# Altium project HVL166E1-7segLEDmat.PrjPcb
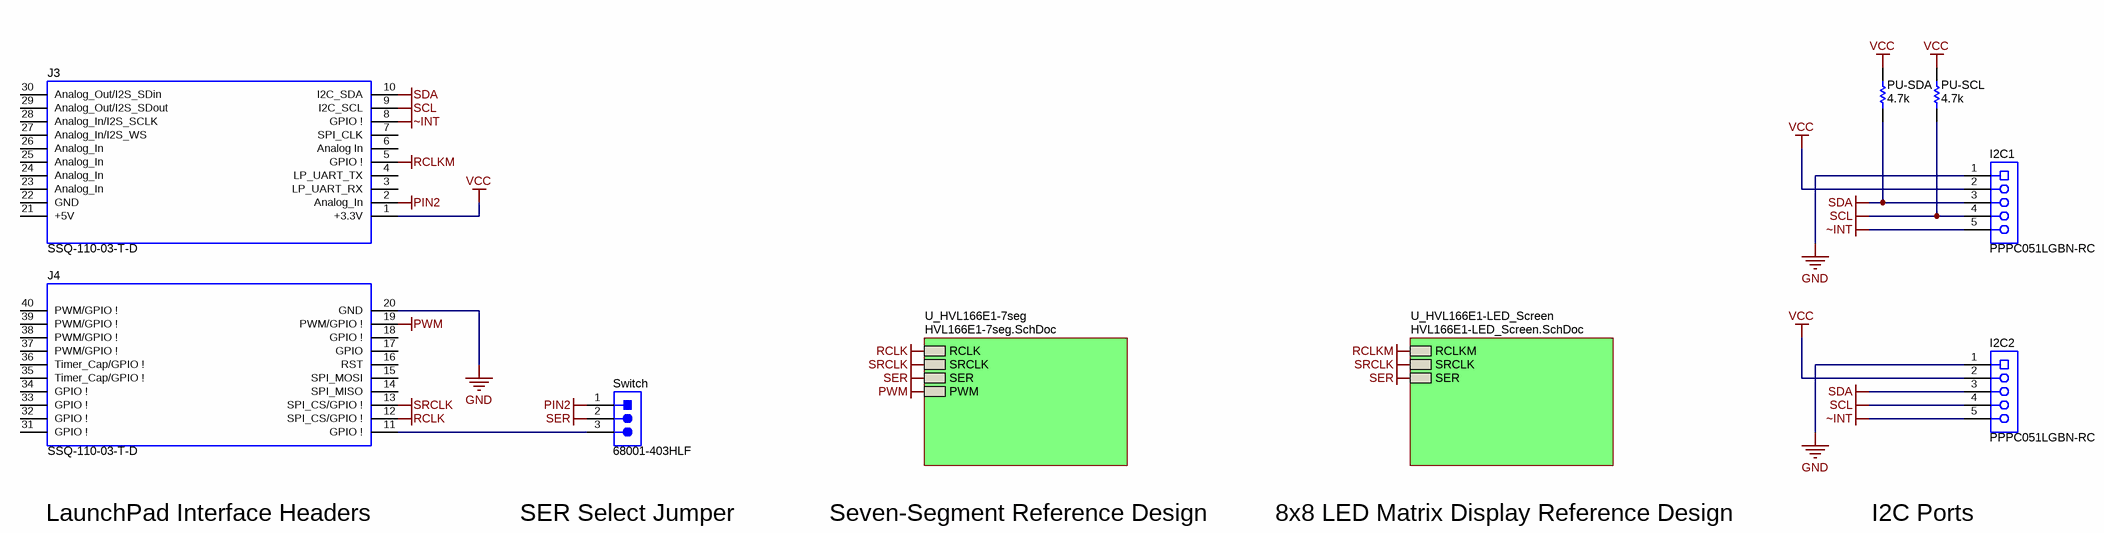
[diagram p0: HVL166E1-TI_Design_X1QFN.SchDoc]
CopyrightYear: 2016; PCB_Layout: Daniel Hartung; PCB_Rev: E1; PRJ_Customer: Public Release; PRJ_Engineer: Daniel Hartung; PRJ_Number: HVL166; PRJ_Title: BOOSTXL-SHIFTLED; SCH_Rev: E1; TechSupport: http://www.ti.com/support; TID: TIDA-1233
3 sheets, 193 parts. Net scope: hierarchical (ports join the sheet entries above them; power ports are global).
Board file: HVL166E1-7SegPCB.PcbDoc
Sheets:
  HVL166E1-TI_Design_X1QFN.SchDoc
    U_HVL166E1-7seg = HVL166E1-7seg.SchDoc
    U_HVL166E1-LED_Screen = HVL166E1-LED_Screen.SchDoc

## Sheet HVL166E1-TI_Design_X1QFN.SchDoc
size 431 x 279 mm; Date: Not shown in title block; ApprovedBy: Not shown in title block; CheckedBy: Not shown in title block; Author: Not shown in title block; CompanyName: Not shown in title block; Engineer: Not shown in title block; Organization: Not shown in title block; Address1: Not shown in title block; Address2: Not shown in title block; Address3: Not shown in title block; Address4: Not shown in title block; DocumentNumber: 1; Revision: Use project parameter SCH_Rev; SheetNumber: 1; SheetTotal: 3; PageSetup: Record=PageOptions¦CenterHorizontal=True¦CenterVertical=True¦PrintScale=1.00¦XCorrection=1.00¦YCorrection=1.00¦PrintKind=0¦BorderSize=5000000¦LeftOffset=0¦BottomOffset=0¦Orientation=2¦PaperLength=1000¦PaperWidth=1000¦Scale=100¦PaperSource=15¦PrintQuality=600¦MediaType=1¦DitherType=10¦PaperKind=Letter¦PrintScaleMode=1

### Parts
I2C1  PPPC051LGBN-RC  [CONN_PPPC051LGBN]
I2C2  PPPC051LGBN-RC  [CONN_PPPC051LGBN]
J3  SSQ-110-03-T-D  [BoosterPack_40pin_J1J3]
J4  SSQ-110-03-T-D  [BoosterPack_40pin_J2J4]
PU-SCL  ValueDisplayed: 4.7k  [0603]  (hidden comment: CRCW06034K70JNEA)
PU-SDA  ValueDisplayed: 4.7k  [0603]  (hidden comment: CRCW06034K70JNEA)
Switch  68001-403HLF  [FCI_68001-403HLF]

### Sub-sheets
U_HVL166E1-7seg = HVL166E1-7seg.SchDoc: RCLK, SRCLK, SER, PWM
U_HVL166E1-LED_Screen = HVL166E1-LED_Screen.SchDoc: RCLKM, SRCLK, SER

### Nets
GND: I2C1.1 I2C2.1 J4.20(GND)
PIN2: J3.2(Analog_In) Switch.1
PWM: J4.19(PWM/GPIO_!) ; sheet U_HVL166E1-7seg/PWM
RCLK: J4.12(SPI_CS/GPIO_!) ; sheet U_HVL166E1-7seg/RCLK
RCLKM: J3.5(GPIO_!) ; sheet U_HVL166E1-LED_Screen/RCLKM
SCL: I2C1.4 I2C2.4 J3.9(I2C_SCL) PU-SCL.1
SDA: I2C1.3 I2C2.3 J3.10(I2C_SDA) PU-SDA.1
SER: Switch.2 ; sheet U_HVL166E1-7seg/SER, sheet U_HVL166E1-LED_Screen/SER
SRCLK: J4.13(SPI_CS/GPIO_!) ; sheet U_HVL166E1-7seg/SRCLK, sheet U_HVL166E1-LED_Screen/SRCLK
VCC: I2C1.2 I2C2.2 J3.1(+3.3V) PU-SCL.2 PU-SDA.2
~INT: I2C1.5 I2C2.5 J3.8(GPIO_!)
NetJ4_11: J4.11(GPIO_!) Switch.3

Not connected (* = marked no-connect by the designer): J3 3(LP_UART_RX) 4(LP_UART_TX) 6(Analog_In) 7(SPI_CLK) 21(+5V) 22(GND) 23(Analog_In) 24(Analog_In) 25(Analog_In) 26(Analog_In) 27(Analog_In/I2S_WS) 28(Analog_In/I2S_SCLK) 29(Analog_Out/I2S_SDout) 30(Analog_Out/I2S_SDin); J4 14(SPI_MISO) 15(SPI_MOSI) 16(RST) 17(GPIO) 18(GPIO_!) 31(GPIO_!) 32(GPIO_!) 33(GPIO_!) 34(GPIO_!) 35(Timer_Cap/GPIO_!) 36(Timer_Cap/GPIO_!) 37(PWM/GPIO_!) 38(PWM/GPIO_!) 39(PWM/GPIO_!) 40(PWM/GPIO_!)

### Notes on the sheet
- LaunchPad Interface Headers
- SER Select Jumper
- Seven-Segment Reference Design
- 8x8 LED Matrix Display Reference Design
- I2C Ports

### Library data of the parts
I2C1 I2C2 = PPPC051LGBN-RC: Receptacle, 100mil, 5x1, Gold, R/A, TH; Manufacturer: Sullins Connector Solutions; SymbolCreator: a0412235
J3 = BoosterPack_40pin_J1J3: Receptacle, 2.54mm, 10x2, Tin, TH; Manufacturer: Samtec; Alternate Manufacturer: Major League Electronics; Alternate PartNumber: CRD-081413-A-G; SymbolCreator: a0412235; Note: Booster Pack 40 pin J1 and J3
J4 = BoosterPack_40pin_J2J4: Receptacle, 2.54mm, 10x2, Tin, TH; Manufacturer: Samtec; Alternate Manufacturer: Major League Electronics; Alternate PartNumber: CRD-081413-A-G; SymbolCreator: a0412235; Note: Booster Pack 40 pin J2 and J4
PU-SCL PU-SDA = CRCW06034K70JNEA: RES, 4.7 k, 5%, 0.1 W, 0603; Manufacturer: Vishay-Dale; CompType: Resistor; Value: 4.7k; Res_ohm: 4700; Value_Code: 4k70; Tolerance_%: 5; Power_W: 0.1; Value2: 0.1W; VDC_V: 75; TempCo: 200 ppm/C; SizeArea_mm2: 1.28; SizeX_mm: 1.6; SizeY_mm: 0.8; SizeZ_mm: 1; EIA_Code: E24; U/M: EA; AEC Category: Q200
Switch = 68001-403HLF: Header, 2.54mm, 3x1, Tin, TH; Manufacturer: FCI; SymbolCreator: a0799628; Pitch_mm: 2.54; Gender: Male; Shrouded: N; Row_Count: 1; Current_A: 3; Voltage_V: 1500; Cert_CSA: Y

## Sheet HVL166E1-7seg.SchDoc
size 431 x 279 mm; Date: Not shown in title block; ApprovedBy: Not shown in title block; CheckedBy: Not shown in title block; Author: Not shown in title block; CompanyName: Not shown in title block; Engineer: Not shown in title block; Organization: Not shown in title block; Address1: Not shown in title block; Address2: Not shown in title block; Address3: Not shown in title block; Address4: Not shown in title block; DocumentNumber: 1; Revision: Use project parameter SCH_Rev; SheetNumber: 2; SheetTotal: 3; PageSetup: Record=PageOptions¦CenterHorizontal=True¦CenterVertical=True¦PrintScale=1.00¦XCorrection=1.00¦YCorrection=1.00¦PrintKind=0¦BorderSize=5000000¦LeftOffset=0¦BottomOffset=0¦Orientation=2¦PaperLength=1000¦PaperWidth=1000¦Scale=100¦PaperSource=15¦PrintQuality=600¦MediaType=1¦DitherType=10¦PaperKind=Letter¦PrintScaleMode=1
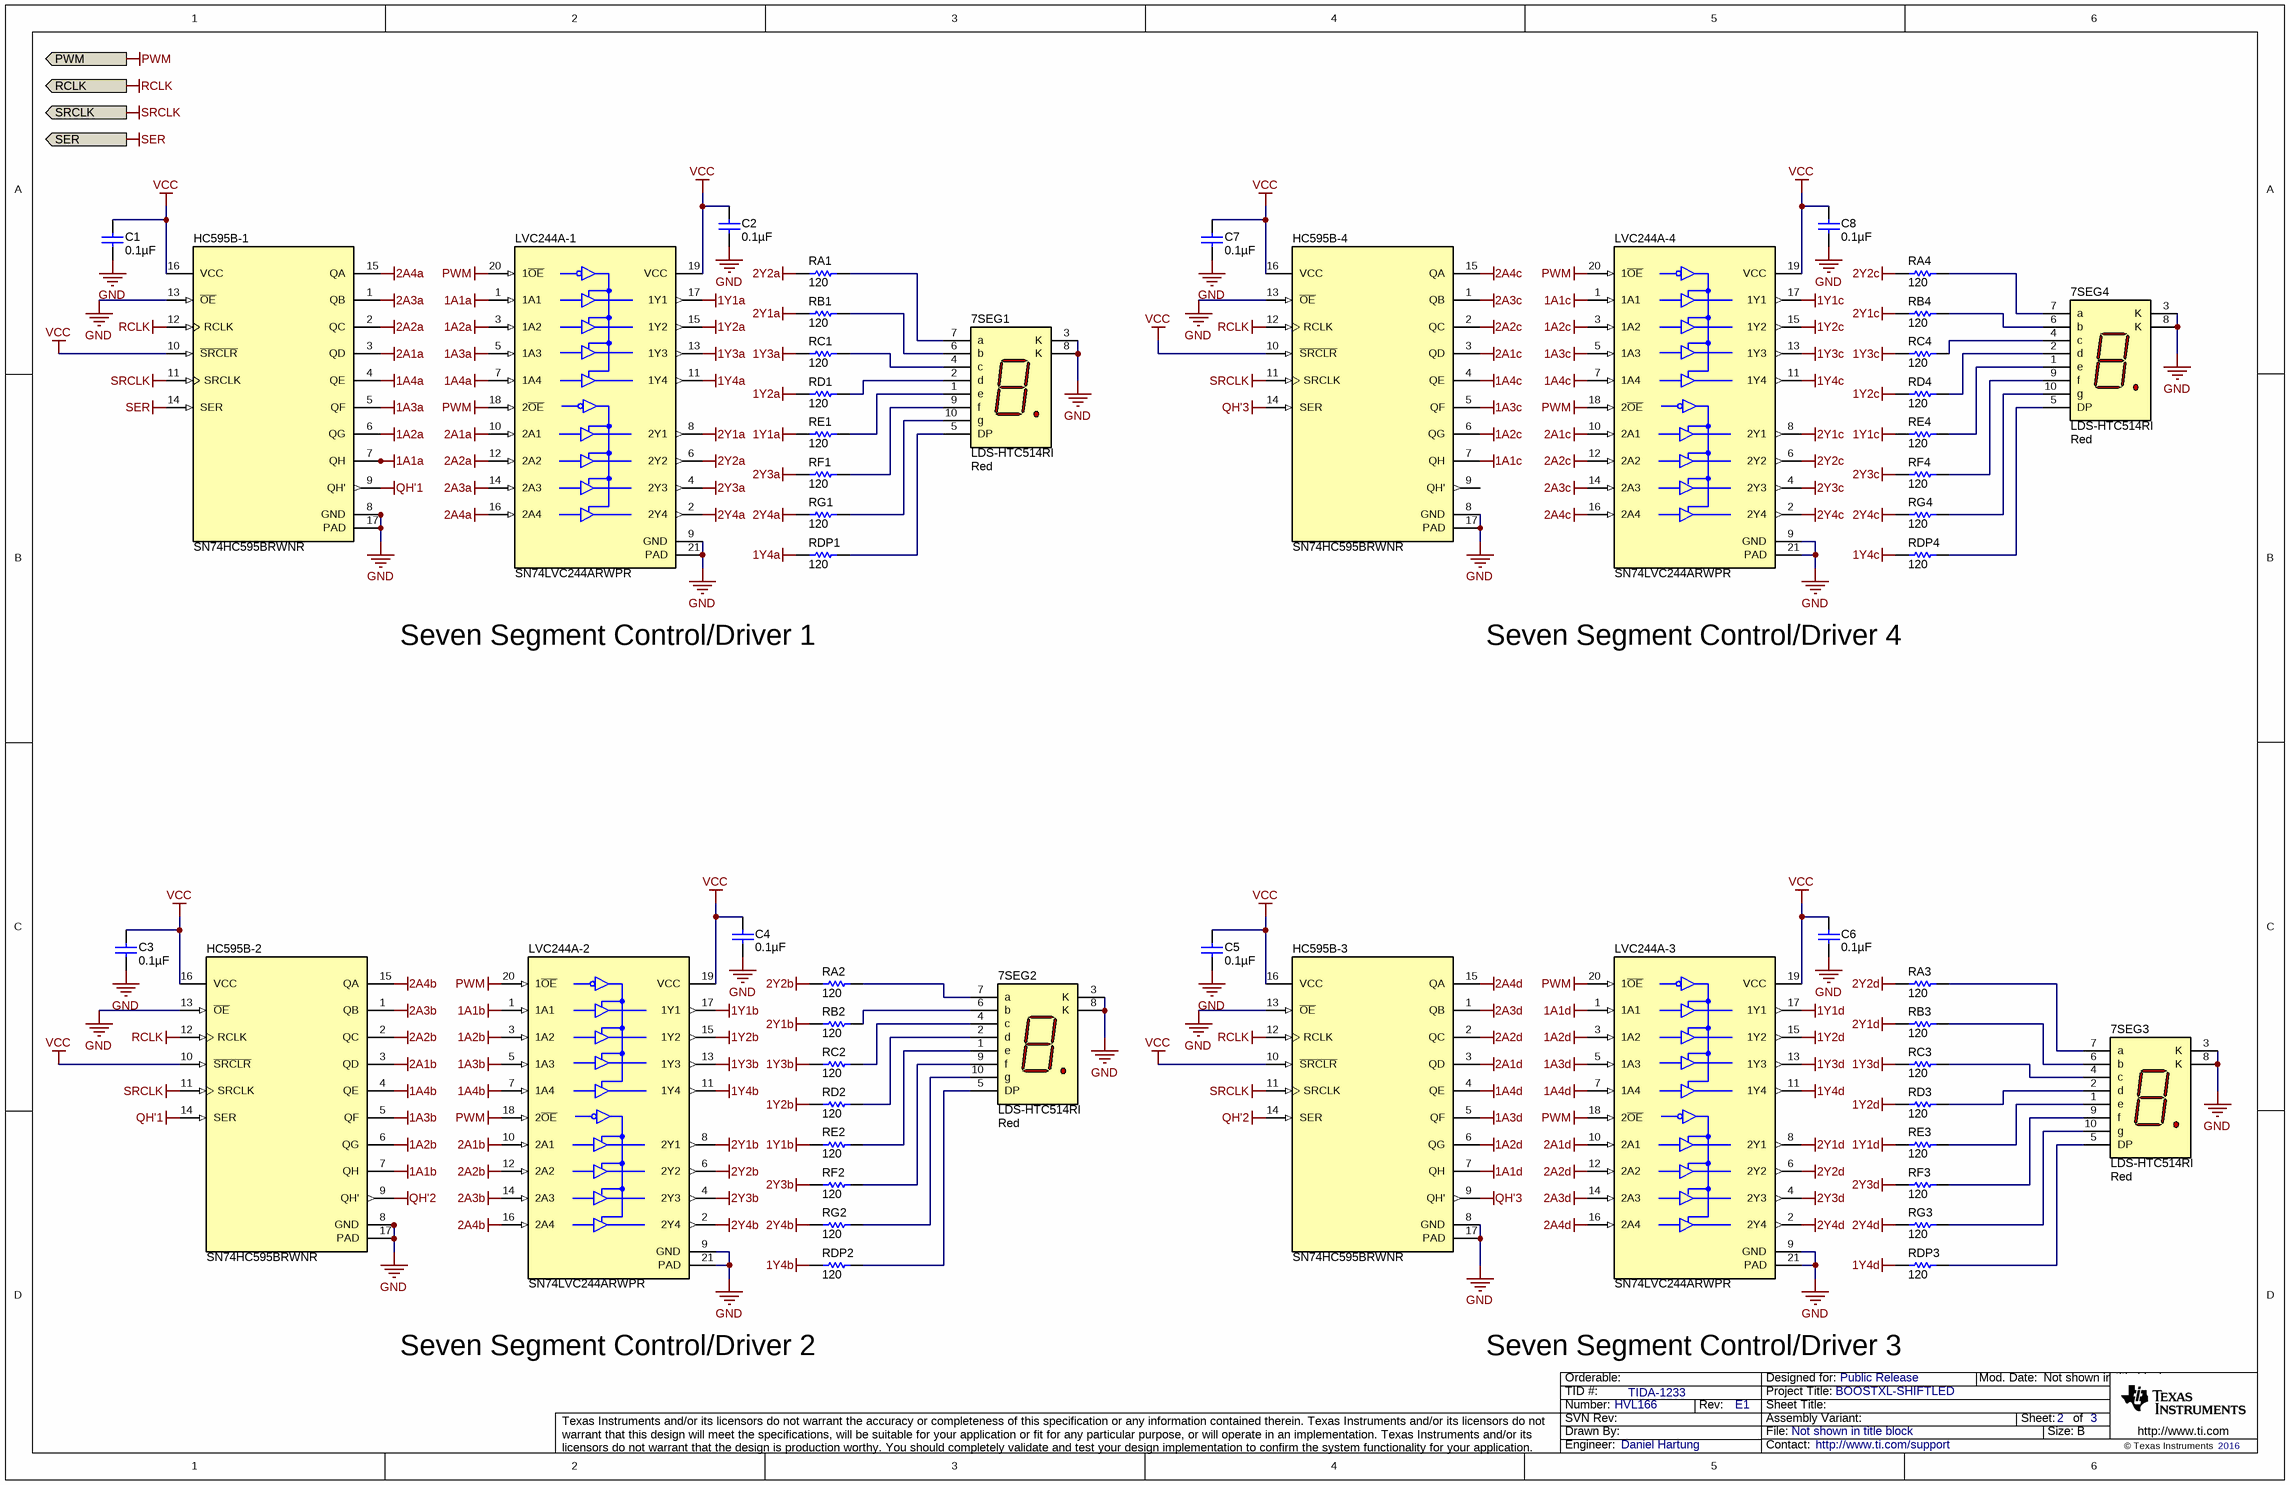
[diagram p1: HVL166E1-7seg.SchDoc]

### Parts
(Parts that share a designator on the sheet are numbered #1, #2 ... from top to bottom, then left to right.)
7SEG1  LDS-HTC514RI  value Red  [LDS-A514RI_Red]
7SEG2  LDS-HTC514RI  value Red  [LDS-A514RI_Red]
7SEG3  LDS-HTC514RI  value Red  [LDS-A514RI_Red]
7SEG4  LDS-HTC514RI  value Red  [LDS-A514RI_Red]
C1  ValueDisplayed: 0.1µF  [0402_065]  (hidden comment: 160R07X104KV4T)
C2  ValueDisplayed: 0.1µF  [0402_065]  (hidden comment: 160R07X104KV4T)
C3  ValueDisplayed: 0.1µF  [0402_065]  (hidden comment: 160R07X104KV4T)
C4  ValueDisplayed: 0.1µF  [0402_065]  (hidden comment: 160R07X104KV4T)
C5  ValueDisplayed: 0.1µF  [0402_065]  (hidden comment: 160R07X104KV4T)
C6  ValueDisplayed: 0.1µF  [0402_065]  (hidden comment: 160R07X104KV4T)
C7  ValueDisplayed: 0.1µF  [0402_065]  (hidden comment: 160R07X104KV4T)
C8  ValueDisplayed: 0.1µF  [0402_065]  (hidden comment: 160R07X104KV4T)
HC595B-1  SN74HC595BRWNR  [RWN0016A]
HC595B-2  SN74HC595BRWNR  [RWN0016A]
HC595B-3  SN74HC595BRWNR  [RWN0016A]
HC595B-4  SN74HC595BRWNR  [RWN0016A]
LVC244A-1  SN74LVC244ARWPR  [RWP0020A]
LVC244A-2  SN74LVC244ARWPR  [RWP0020A]
LVC244A-3  SN74LVC244ARWPR  [RWP0020A]
LVC244A-4  SN74LVC244ARWPR  [RWP0020A]
RA1#1  ValueDisplayed: 120  [0402]  (hidden comment: CRCW0402120RJNED)
RA2#1  ValueDisplayed: 120  [0402]  (hidden comment: CRCW0402120RJNED)
RA3#1  ValueDisplayed: 120  [0402]  (hidden comment: CRCW0402120RJNED)
RA4#1  ValueDisplayed: 120  [0402]  (hidden comment: CRCW0402120RJNED)
RB1#1  ValueDisplayed: 120  [0402]  (hidden comment: CRCW0402120RJNED)
RB2#1  ValueDisplayed: 120  [0402]  (hidden comment: CRCW0402120RJNED)
RB3#1  ValueDisplayed: 120  [0402]  (hidden comment: CRCW0402120RJNED)
RB4#1  ValueDisplayed: 120  [0402]  (hidden comment: CRCW0402120RJNED)
RC1#1  ValueDisplayed: 120  [0402]  (hidden comment: CRCW0402120RJNED)
RC2#1  ValueDisplayed: 120  [0402]  (hidden comment: CRCW0402120RJNED)
RC3#1  ValueDisplayed: 120  [0402]  (hidden comment: CRCW0402120RJNED)
RC4#1  ValueDisplayed: 120  [0402]  (hidden comment: CRCW0402120RJNED)
RD1#1  ValueDisplayed: 120  [0402]  (hidden comment: CRCW0402120RJNED)
RD2#1  ValueDisplayed: 120  [0402]  (hidden comment: CRCW0402120RJNED)
RD3#1  ValueDisplayed: 120  [0402]  (hidden comment: CRCW0402120RJNED)
RD4#1  ValueDisplayed: 120  [0402]  (hidden comment: CRCW0402120RJNED)
RDP1  ValueDisplayed: 120  [0402]  (hidden comment: CRCW0402120RJNED)
RDP2  ValueDisplayed: 120  [0402]  (hidden comment: CRCW0402120RJNED)
RDP3  ValueDisplayed: 120  [0402]  (hidden comment: CRCW0402120RJNED)
RDP4  ValueDisplayed: 120  [0402]  (hidden comment: CRCW0402120RJNED)
RE1#1  ValueDisplayed: 120  [0402]  (hidden comment: CRCW0402120RJNED)
RE2#1  ValueDisplayed: 120  [0402]  (hidden comment: CRCW0402120RJNED)
RE3#1  ValueDisplayed: 120  [0402]  (hidden comment: CRCW0402120RJNED)
RE4#1  ValueDisplayed: 120  [0402]  (hidden comment: CRCW0402120RJNED)
RF1#1  ValueDisplayed: 120  [0402]  (hidden comment: CRCW0402120RJNED)
RF2#1  ValueDisplayed: 120  [0402]  (hidden comment: CRCW0402120RJNED)
RF3#1  ValueDisplayed: 120  [0402]  (hidden comment: CRCW0402120RJNED)
RF4#1  ValueDisplayed: 120  [0402]  (hidden comment: CRCW0402120RJNED)
RG1#1  ValueDisplayed: 120  [0402]  (hidden comment: CRCW0402120RJNED)
RG2#1  ValueDisplayed: 120  [0402]  (hidden comment: CRCW0402120RJNED)
RG3#1  ValueDisplayed: 120  [0402]  (hidden comment: CRCW0402120RJNED)
RG4#1  ValueDisplayed: 120  [0402]  (hidden comment: CRCW0402120RJNED)

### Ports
PWM, RCLK, SER, SRCLK

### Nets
1A1a: HC595B-1.7(QH) LVC244A-1.1(1A1)
1A1b: HC595B-2.7(QH) LVC244A-2.1(1A1)
1A1c: HC595B-4.7(QH) LVC244A-4.1(1A1)
1A1d: HC595B-3.7(QH) LVC244A-3.1(1A1)
1A2a: HC595B-1.6(QG) LVC244A-1.3(1A2)
1A2b: HC595B-2.6(QG) LVC244A-2.3(1A2)
1A2c: HC595B-4.6(QG) LVC244A-4.3(1A2)
1A2d: HC595B-3.6(QG) LVC244A-3.3(1A2)
1A3a: HC595B-1.5(QF) LVC244A-1.5(1A3)
1A3b: HC595B-2.5(QF) LVC244A-2.5(1A3)
1A3c: HC595B-4.5(QF) LVC244A-4.5(1A3)
1A3d: HC595B-3.5(QF) LVC244A-3.5(1A3)
1A4a: HC595B-1.4(QE) LVC244A-1.7(1A4)
1A4b: HC595B-2.4(QE) LVC244A-2.7(1A4)
1A4c: HC595B-4.4(QE) LVC244A-4.7(1A4)
1A4d: HC595B-3.4(QE) LVC244A-3.7(1A4)
1Y1a: LVC244A-1.17(1Y1) RE1#1.1
1Y1b: LVC244A-2.17(1Y1) RE2#1.1
1Y1c: LVC244A-4.17(1Y1) RE4#1.1
1Y1d: LVC244A-3.17(1Y1) RE3#1.1
1Y2a: LVC244A-1.15(1Y2) RD1#1.1
1Y2b: LVC244A-2.15(1Y2) RD2#1.1
1Y2c: LVC244A-4.15(1Y2) RD4#1.1
1Y2d: LVC244A-3.15(1Y2) RD3#1.1
1Y3a: LVC244A-1.13(1Y3) RC1#1.1
1Y3b: LVC244A-2.13(1Y3) RC2#1.1
1Y3c: LVC244A-4.13(1Y3) RC4#1.1
1Y3d: LVC244A-3.13(1Y3) RC3#1.1
1Y4a: LVC244A-1.11(1Y4) RDP1.1
1Y4b: LVC244A-2.11(1Y4) RDP2.1
1Y4c: LVC244A-4.11(1Y4) RDP4.1
1Y4d: LVC244A-3.11(1Y4) RDP3.1
2A1a: HC595B-1.3(QD) LVC244A-1.10(2A1)
2A1b: HC595B-2.3(QD) LVC244A-2.10(2A1)
2A1c: HC595B-4.3(QD) LVC244A-4.10(2A1)
2A1d: HC595B-3.3(QD) LVC244A-3.10(2A1)
2A2a: HC595B-1.2(QC) LVC244A-1.12(2A2)
2A2b: HC595B-2.2(QC) LVC244A-2.12(2A2)
2A2c: HC595B-4.2(QC) LVC244A-4.12(2A2)
2A2d: HC595B-3.2(QC) LVC244A-3.12(2A2)
2A3a: HC595B-1.1(QB) LVC244A-1.14(2A3)
2A3b: HC595B-2.1(QB) LVC244A-2.14(2A3)
2A3c: HC595B-4.1(QB) LVC244A-4.14(2A3)
2A3d: HC595B-3.1(QB) LVC244A-3.14(2A3)
2A4a: HC595B-1.15(QA) LVC244A-1.16(2A4)
2A4b: HC595B-2.15(QA) LVC244A-2.16(2A4)
2A4c: HC595B-4.15(QA) LVC244A-4.16(2A4)
2A4d: HC595B-3.15(QA) LVC244A-3.16(2A4)
2Y1a: LVC244A-1.8(2Y1) RB1#1.1
2Y1b: LVC244A-2.8(2Y1) RB2#1.1
2Y1c: LVC244A-4.8(2Y1) RB4#1.1
2Y1d: LVC244A-3.8(2Y1) RB3#1.1
2Y2a: LVC244A-1.6(2Y2) RA1#1.1
2Y2b: LVC244A-2.6(2Y2) RA2#1.1
2Y2c: LVC244A-4.6(2Y2) RA4#1.1
2Y2d: LVC244A-3.6(2Y2) RA3#1.1
2Y3a: LVC244A-1.4(2Y3) RF1#1.1
2Y3b: LVC244A-2.4(2Y3) RF2#1.1
2Y3c: LVC244A-4.4(2Y3) RF4#1.1
2Y3d: LVC244A-3.4(2Y3) RF3#1.1
2Y4a: LVC244A-1.2(2Y4) RG1#1.1
2Y4b: LVC244A-2.2(2Y4) RG2#1.1
2Y4c: LVC244A-4.2(2Y4) RG4#1.1
2Y4d: LVC244A-3.2(2Y4) RG3#1.1
GND: 7SEG1.3(K) 7SEG1.8(K) 7SEG2.3(K) 7SEG2.8(K) 7SEG3.3(K) 7SEG3.8(K) 7SEG4.3(K) 7SEG4.8(K) C1.2 C2.2 C3.2 C4.2 C5.2 C6.2 C7.2 C8.2 HC595B-1.8(GND) HC595B-1.13(~{OE}) HC595B-1.17(PAD) HC595B-2.8(GND) HC595B-2.13(~{OE}) HC595B-2.17(PAD) HC595B-3.8(GND) HC595B-3.13(~{OE}) HC595B-3.17(PAD) HC595B-4.8(GND) HC595B-4.13(~{OE}) HC595B-4.17(PAD) LVC244A-1.9(GND) LVC244A-1.21(PAD) LVC244A-2.9(GND) LVC244A-2.21(PAD) LVC244A-3.9(GND) LVC244A-3.21(PAD) LVC244A-4.9(GND) LVC244A-4.21(PAD)
PWM: LVC244A-1.18(2~{OE}) LVC244A-1.20(1~{OE}) LVC244A-2.18(2~{OE}) LVC244A-2.20(1~{OE}) LVC244A-3.18(2~{OE}) LVC244A-3.20(1~{OE}) LVC244A-4.18(2~{OE}) LVC244A-4.20(1~{OE}) ; port PWM
QH'1: HC595B-1.9(QH') HC595B-2.14(SER)
QH'2: HC595B-2.9(QH') HC595B-3.14(SER)
QH'3: HC595B-3.9(QH') HC595B-4.14(SER)
RCLK: HC595B-1.12(RCLK) HC595B-2.12(RCLK) HC595B-3.12(RCLK) HC595B-4.12(RCLK) ; port RCLK
SER: HC595B-1.14(SER) ; port SER
SRCLK: HC595B-1.11(SRCLK) HC595B-2.11(SRCLK) HC595B-3.11(SRCLK) HC595B-4.11(SRCLK) ; port SRCLK
VCC: C1.1 C2.1 C3.1 C4.1 C5.1 C6.1 C7.1 C8.1 HC595B-1.10(~{SRCLR}) HC595B-1.16(VCC) HC595B-2.10(~{SRCLR}) HC595B-2.16(VCC) HC595B-3.10(~{SRCLR}) HC595B-3.16(VCC) HC595B-4.10(~{SRCLR}) HC595B-4.16(VCC) LVC244A-1.19(VCC) LVC244A-2.19(VCC) LVC244A-3.19(VCC) LVC244A-4.19(VCC)
Net7SEG1_1: 7SEG1.1(e) RE1#1.2
Net7SEG1_2: 7SEG1.2(d) RD1#1.2
Net7SEG1_4: 7SEG1.4(c) RC1#1.2
Net7SEG1_5: 7SEG1.5(DP) RDP1.2
Net7SEG1_6: 7SEG1.6(b) RB1#1.2
Net7SEG1_7: 7SEG1.7(a) RA1#1.2
Net7SEG1_9: 7SEG1.9(f) RF1#1.2
Net7SEG1_10: 7SEG1.10(g) RG1#1.2
Net7SEG2_1: 7SEG2.1(e) RE2#1.2
Net7SEG2_2: 7SEG2.2(d) RD2#1.2
Net7SEG2_4: 7SEG2.4(c) RC2#1.2
Net7SEG2_5: 7SEG2.5(DP) RDP2.2
Net7SEG2_6: 7SEG2.6(b) RB2#1.2
Net7SEG2_7: 7SEG2.7(a) RA2#1.2
Net7SEG2_9: 7SEG2.9(f) RF2#1.2
Net7SEG2_10: 7SEG2.10(g) RG2#1.2
Net7SEG3_1: 7SEG3.1(e) RE3#1.2
Net7SEG3_2: 7SEG3.2(d) RD3#1.2
Net7SEG3_4: 7SEG3.4(c) RC3#1.2
Net7SEG3_5: 7SEG3.5(DP) RDP3.2
Net7SEG3_6: 7SEG3.6(b) RB3#1.2
Net7SEG3_7: 7SEG3.7(a) RA3#1.2
Net7SEG3_9: 7SEG3.9(f) RF3#1.2
Net7SEG3_10: 7SEG3.10(g) RG3#1.2
Net7SEG4_1: 7SEG4.1(e) RE4#1.2
Net7SEG4_2: 7SEG4.2(d) RD4#1.2
Net7SEG4_4: 7SEG4.4(c) RC4#1.2
Net7SEG4_5: 7SEG4.5(DP) RDP4.2
Net7SEG4_6: 7SEG4.6(b) RB4#1.2
Net7SEG4_7: 7SEG4.7(a) RA4#1.2
Net7SEG4_9: 7SEG4.9(f) RF4#1.2
Net7SEG4_10: 7SEG4.10(g) RG4#1.2

Not connected (* = marked no-connect by the designer): HC595B-4 9(QH')

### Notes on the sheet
- Seven Segment Control/Driver 1
- Seven Segment Control/Driver 4
- Seven Segment Control/Driver 2
- Seven Segment Control/Driver 3

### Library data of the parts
7SEG1-7SEG4 = LDS-HTC514RI: LED, Red, TH; Manufacturer: Lumex; SymbolCreator: Altium; Vf_V: 2.1; Value2: 2.1V; Io_A: 0.01; Vr_V: 5; Ir_A: 0.0001; Tjmax_C: 105; Power_TotalModule: 0.105; Value1: 0.105W; SizeAreaWB_mm2: 306.6; SizeArea_mm2: 239.4; SizeX_mm: 19; SizeY_mm: 12.6; SizeZ_mm: 8.25; U/M: EA
C1-C8 = 160R07X104KV4T: CAP, CERM, 0.1 µF, 16 V, +/- 10%, X5R, 0402; Manufacturer: Johanson Technology; Polarized: N; CompType: Capacitor; Value: 0.1uF; U/M: EA; Cap_F: 0.0000001; Tolerance_%: 10; Value1: Unknown; VDC_V: 16; Value2: 16V; TaMin_C: -55; TaMax_C: 85; Cap_Case: 0402; SizeArea_mm2: 0.5; SizeAreaWB_mm2: 3; SizeX_mm: 1; SizeZ_mm: 0.65; AEC Category: Q200
HC595B-1-HC595B-4 = SN74HC595BRWNR: 8-Bit Shift Registers With 3-State Output Register, RWN0016A; Manufacturer: Texas Instruments; SymbolCreator: Altium; SizeArea_mm2: 6.25; SizeAreaWB_mm2: 12.25; SizeX_mm: 2.5; SizeZ_mm: 0.5; CompType: IC; U/M: EA
LVC244A-1-LVC244A-4 = SN74LVC244ARWPR: Octal Buffer or Driver With 3-State Output, RWP0020A; Manufacturer: Texas Instruments; SymbolCreator: Altium; SizeArea_mm2: 8.25; SizeAreaWB_mm2: 15.05; SizeX_mm: 2.5; SizeY_mm: 3.3; SizeZ_mm: 0.5; CompType: IC; U/M: EA
RA1#1 RA2#1 RA3#1 RA4#1 RB1#1 RB2#1 RB3#1 RB4#1 RC1#1 RC2#1 RC3#1 RC4#1 RD1#1 RD2#1 RD3#1 RD4#1 RDP1-RDP4 RE1#1 RE2#1 RE3#1 RE4#1 RF1#1 RF2#1 RF3#1 RF4#1 RG1#1 RG2#1 RG3#1 RG4#1 = CRCW0402120RJNED: RES, 120, 5%, 0.063 W, 0402; Manufacturer: Vishay-Dale; CompType: Resistor; Value: 120; Value_Code: 120R; Tolerance_%: 5; Power_W: 0.063; Value2: 0.063W; VDC_V: 50; TempCo: 200 ppm/C; EIA_Code: E24; U/M: EA; AEC Category: Q200

## Sheet HVL166E1-LED_Screen.SchDoc
size 431 x 279 mm; Date: Not shown in title block; ApprovedBy: Not shown in title block; CheckedBy: Not shown in title block; Author: Not shown in title block; CompanyName: Not shown in title block; Engineer: Not shown in title block; Organization: Not shown in title block; Address1: Not shown in title block; Address2: Not shown in title block; Address3: Not shown in title block; Address4: Not shown in title block; DocumentNumber: 1; Revision: Use project parameter SCH_Rev; SheetNumber: 3; SheetTotal: 3; PageSetup: Record=PageOptions¦CenterHorizontal=True¦CenterVertical=True¦PrintScale=1.00¦XCorrection=1.00¦YCorrection=1.00¦PrintKind=0¦BorderSize=5000000¦LeftOffset=0¦BottomOffset=0¦Orientation=2¦PaperLength=1000¦PaperWidth=1000¦Scale=100¦PaperSource=15¦PrintQuality=600¦MediaType=1¦DitherType=10¦PaperKind=Letter¦PrintScaleMode=1
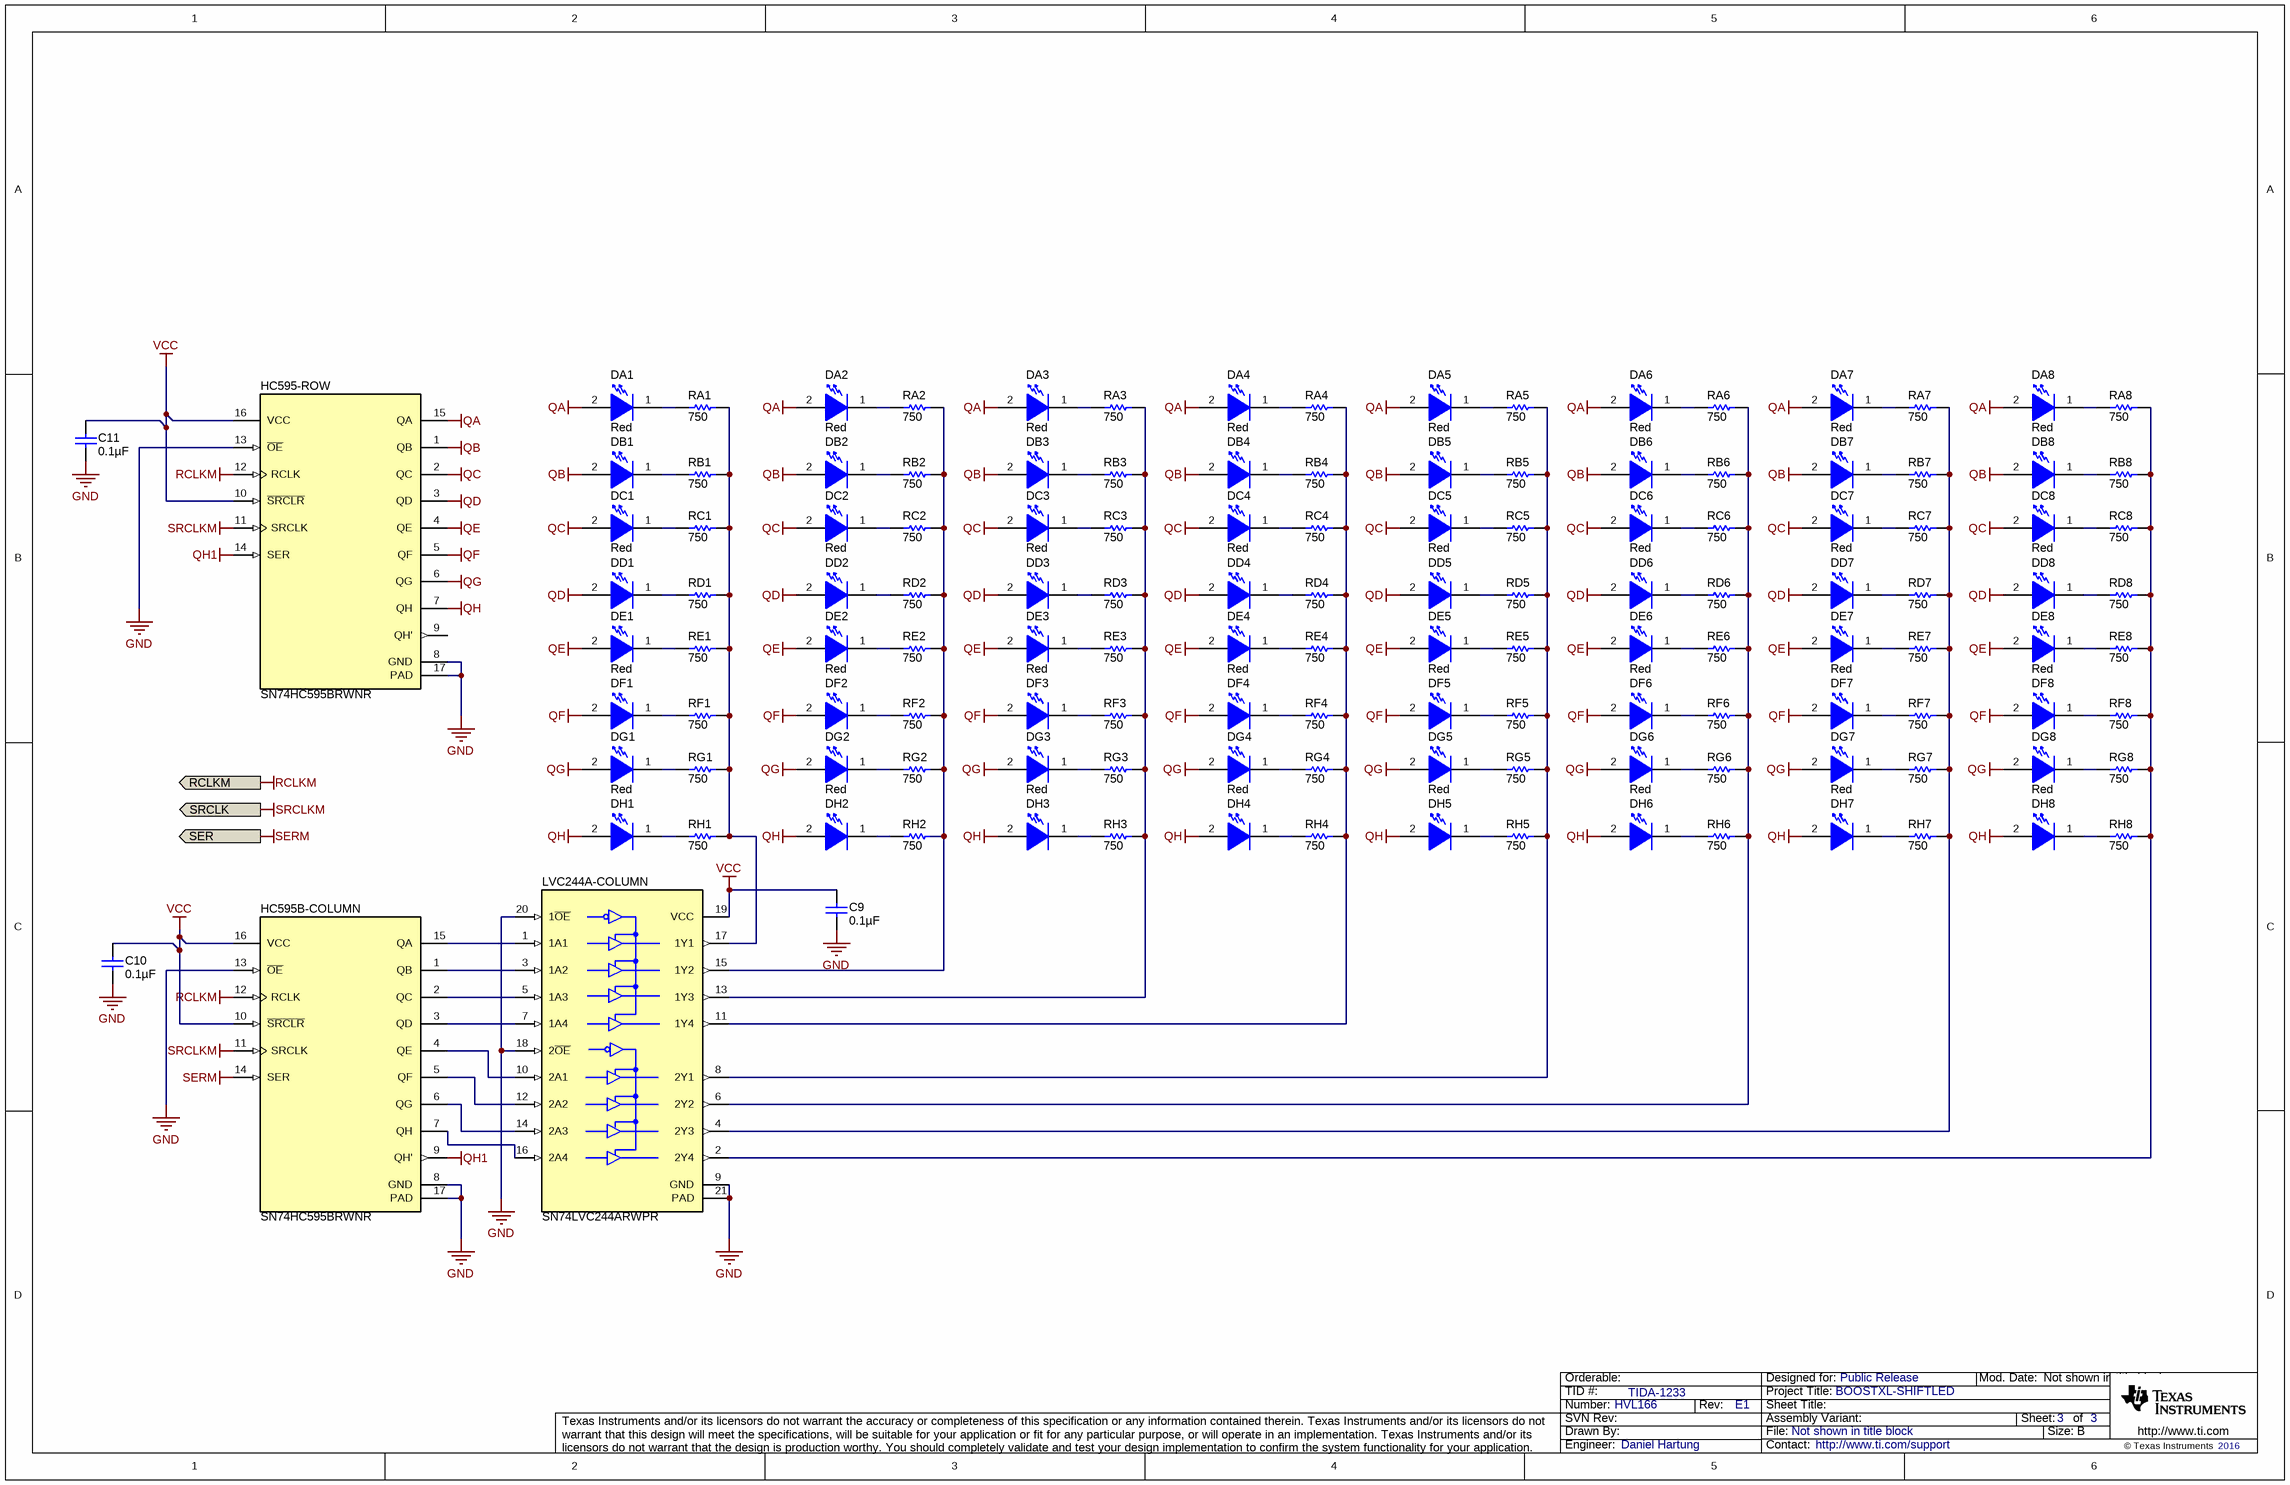
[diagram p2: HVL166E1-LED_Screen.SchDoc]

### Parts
(Parts that share a designator on the sheet are numbered #1, #2 ... from top to bottom, then left to right.)
C9  ValueDisplayed: 0.1µF  [0402_065]  (hidden comment: 160R07X104KV4T)
C10  ValueDisplayed: 0.1µF  [0402_065]  (hidden comment: 160R07X104KV4T)
C11  ValueDisplayed: 0.1µF  [0402_065]  (hidden comment: 160R07X104KV4T)
DA1  value Red  [SML-31_Red]  (hidden comment: SML-311UTT86)
DA2  value Red  [SML-31_Red]  (hidden comment: SML-311UTT86)
DA3  value Red  [SML-31_Red]  (hidden comment: SML-311UTT86)
DA4  value Red  [SML-31_Red]  (hidden comment: SML-311UTT86)
DA5  value Red  [SML-31_Red]  (hidden comment: SML-311UTT86)
DA6  value Red  [SML-31_Red]  (hidden comment: SML-311UTT86)
DA7  value Red  [SML-31_Red]  (hidden comment: SML-311UTT86)
DA8  value Red  [SML-31_Red]  (hidden comment: SML-311UTT86)
DB1  SML-311UTT86  [SML-31_Red]  (value not drawn)
DB2  SML-311UTT86  [SML-31_Red]  (value not drawn)
DB3  SML-311UTT86  [SML-31_Red]  (value not drawn)
DB4  SML-311UTT86  [SML-31_Red]  (value not drawn)
DB5  SML-311UTT86  [SML-31_Red]  (value not drawn)
DB6  SML-311UTT86  [SML-31_Red]  (value not drawn)
DB7  SML-311UTT86  [SML-31_Red]  (value not drawn)
DB8  SML-311UTT86  [SML-31_Red]  (value not drawn)
DC1  value Red  [SML-31_Red]  (hidden comment: SML-311UTT86)
DC2  value Red  [SML-31_Red]  (hidden comment: SML-311UTT86)
DC3  value Red  [SML-31_Red]  (hidden comment: SML-311UTT86)
DC4  value Red  [SML-31_Red]  (hidden comment: SML-311UTT86)
DC5  value Red  [SML-31_Red]  (hidden comment: SML-311UTT86)
DC6  value Red  [SML-31_Red]  (hidden comment: SML-311UTT86)
DC7  value Red  [SML-31_Red]  (hidden comment: SML-311UTT86)
DC8  value Red  [SML-31_Red]  (hidden comment: SML-311UTT86)
DD1  SML-311UTT86  [SML-31_Red]  (value not drawn)
DD2  SML-311UTT86  [SML-31_Red]  (value not drawn)
DD3  SML-311UTT86  [SML-31_Red]  (value not drawn)
DD4  SML-311UTT86  [SML-31_Red]  (value not drawn)
DD5  SML-311UTT86  [SML-31_Red]  (value not drawn)
DD6  SML-311UTT86  [SML-31_Red]  (value not drawn)
DD7  SML-311UTT86  [SML-31_Red]  (value not drawn)
DD8  SML-311UTT86  [SML-31_Red]  (value not drawn)
DE1  value Red  [SML-31_Red]  (hidden comment: SML-311UTT86)
DE2  value Red  [SML-31_Red]  (hidden comment: SML-311UTT86)
DE3  value Red  [SML-31_Red]  (hidden comment: SML-311UTT86)
DE4  value Red  [SML-31_Red]  (hidden comment: SML-311UTT86)
DE5  value Red  [SML-31_Red]  (hidden comment: SML-311UTT86)
DE6  value Red  [SML-31_Red]  (hidden comment: SML-311UTT86)
DE7  value Red  [SML-31_Red]  (hidden comment: SML-311UTT86)
DE8  value Red  [SML-31_Red]  (hidden comment: SML-311UTT86)
DF1  SML-311UTT86  [SML-31_Red]  (value not drawn)
DF2  SML-311UTT86  [SML-31_Red]  (value not drawn)
DF3  SML-311UTT86  [SML-31_Red]  (value not drawn)
DF4  SML-311UTT86  [SML-31_Red]  (value not drawn)
DF5  SML-311UTT86  [SML-31_Red]  (value not drawn)
DF6  SML-311UTT86  [SML-31_Red]  (value not drawn)
DF7  SML-311UTT86  [SML-31_Red]  (value not drawn)
DF8  SML-311UTT86  [SML-31_Red]  (value not drawn)
DG1  value Red  [SML-31_Red]  (hidden comment: SML-311UTT86)
DG2  value Red  [SML-31_Red]  (hidden comment: SML-311UTT86)
DG3  value Red  [SML-31_Red]  (hidden comment: SML-311UTT86)
DG4  value Red  [SML-31_Red]  (hidden comment: SML-311UTT86)
DG5  value Red  [SML-31_Red]  (hidden comment: SML-311UTT86)
DG6  value Red  [SML-31_Red]  (hidden comment: SML-311UTT86)
DG7  value Red  [SML-31_Red]  (hidden comment: SML-311UTT86)
DG8  value Red  [SML-31_Red]  (hidden comment: SML-311UTT86)
DH1  SML-311UTT86  [SML-31_Red]  (value not drawn)
DH2  SML-311UTT86  [SML-31_Red]  (value not drawn)
DH3  SML-311UTT86  [SML-31_Red]  (value not drawn)
DH4  SML-311UTT86  [SML-31_Red]  (value not drawn)
DH5  SML-311UTT86  [SML-31_Red]  (value not drawn)
DH6  SML-311UTT86  [SML-31_Red]  (value not drawn)
DH7  SML-311UTT86  [SML-31_Red]  (value not drawn)
DH8  SML-311UTT86  [SML-31_Red]  (value not drawn)
HC595-ROW  SN74HC595BRWNR  [RWN0016A]
HC595B-COLUMN  SN74HC595BRWNR  [RWN0016A]
LVC244A-COLUMN  SN74LVC244ARWPR  [RWP0020A]
RA1#2  ValueDisplayed: 750  [0402]  (hidden comment: CRCW0402750RJNED)
RA2#2  ValueDisplayed: 750  [0402]  (hidden comment: CRCW0402750RJNED)
RA3#2  ValueDisplayed: 750  [0402]  (hidden comment: CRCW0402750RJNED)
RA4#2  ValueDisplayed: 750  [0402]  (hidden comment: CRCW0402750RJNED)
RA5  ValueDisplayed: 750  [0402]  (hidden comment: CRCW0402750RJNED)
RA6  ValueDisplayed: 750  [0402]  (hidden comment: CRCW0402750RJNED)
RA7  ValueDisplayed: 750  [0402]  (hidden comment: CRCW0402750RJNED)
RA8  ValueDisplayed: 750  [0402]  (hidden comment: CRCW0402750RJNED)
RB1#2  ValueDisplayed: 750  [0402]  (hidden comment: CRCW0402750RJNED)
RB2#2  ValueDisplayed: 750  [0402]  (hidden comment: CRCW0402750RJNED)
RB3#2  ValueDisplayed: 750  [0402]  (hidden comment: CRCW0402750RJNED)
RB4#2  ValueDisplayed: 750  [0402]  (hidden comment: CRCW0402750RJNED)
RB5  ValueDisplayed: 750  [0402]  (hidden comment: CRCW0402750RJNED)
RB6  ValueDisplayed: 750  [0402]  (hidden comment: CRCW0402750RJNED)
RB7  ValueDisplayed: 750  [0402]  (hidden comment: CRCW0402750RJNED)
RB8  ValueDisplayed: 750  [0402]  (hidden comment: CRCW0402750RJNED)
RC1#2  ValueDisplayed: 750  [0402]  (hidden comment: CRCW0402750RJNED)
RC2#2  ValueDisplayed: 750  [0402]  (hidden comment: CRCW0402750RJNED)
RC3#2  ValueDisplayed: 750  [0402]  (hidden comment: CRCW0402750RJNED)
RC4#2  ValueDisplayed: 750  [0402]  (hidden comment: CRCW0402750RJNED)
RC5  ValueDisplayed: 750  [0402]  (hidden comment: CRCW0402750RJNED)
RC6  ValueDisplayed: 750  [0402]  (hidden comment: CRCW0402750RJNED)
RC7  ValueDisplayed: 750  [0402]  (hidden comment: CRCW0402750RJNED)
RC8  ValueDisplayed: 750  [0402]  (hidden comment: CRCW0402750RJNED)
RD1#2  ValueDisplayed: 750  [0402]  (hidden comment: CRCW0402750RJNED)
RD2#2  ValueDisplayed: 750  [0402]  (hidden comment: CRCW0402750RJNED)
RD3#2  ValueDisplayed: 750  [0402]  (hidden comment: CRCW0402750RJNED)
RD4#2  ValueDisplayed: 750  [0402]  (hidden comment: CRCW0402750RJNED)
RD5  ValueDisplayed: 750  [0402]  (hidden comment: CRCW0402750RJNED)
RD6  ValueDisplayed: 750  [0402]  (hidden comment: CRCW0402750RJNED)
RD7  ValueDisplayed: 750  [0402]  (hidden comment: CRCW0402750RJNED)
RD8  ValueDisplayed: 750  [0402]  (hidden comment: CRCW0402750RJNED)
RE1#2  ValueDisplayed: 750  [0402]  (hidden comment: CRCW0402750RJNED)
RE2#2  ValueDisplayed: 750  [0402]  (hidden comment: CRCW0402750RJNED)
RE3#2  ValueDisplayed: 750  [0402]  (hidden comment: CRCW0402750RJNED)
RE4#2  ValueDisplayed: 750  [0402]  (hidden comment: CRCW0402750RJNED)
RE5  ValueDisplayed: 750  [0402]  (hidden comment: CRCW0402750RJNED)
RE6  ValueDisplayed: 750  [0402]  (hidden comment: CRCW0402750RJNED)
RE7  ValueDisplayed: 750  [0402]  (hidden comment: CRCW0402750RJNED)
RE8  ValueDisplayed: 750  [0402]  (hidden comment: CRCW0402750RJNED)
RF1#2  ValueDisplayed: 750  [0402]  (hidden comment: CRCW0402750RJNED)
RF2#2  ValueDisplayed: 750  [0402]  (hidden comment: CRCW0402750RJNED)
RF3#2  ValueDisplayed: 750  [0402]  (hidden comment: CRCW0402750RJNED)
RF4#2  ValueDisplayed: 750  [0402]  (hidden comment: CRCW0402750RJNED)
RF5  ValueDisplayed: 750  [0402]  (hidden comment: CRCW0402750RJNED)
RF6  ValueDisplayed: 750  [0402]  (hidden comment: CRCW0402750RJNED)
RF7  ValueDisplayed: 750  [0402]  (hidden comment: CRCW0402750RJNED)
RF8  ValueDisplayed: 750  [0402]  (hidden comment: CRCW0402750RJNED)
RG1#2  ValueDisplayed: 750  [0402]  (hidden comment: CRCW0402750RJNED)
RG2#2  ValueDisplayed: 750  [0402]  (hidden comment: CRCW0402750RJNED)
RG3#2  ValueDisplayed: 750  [0402]  (hidden comment: CRCW0402750RJNED)
RG4#2  ValueDisplayed: 750  [0402]  (hidden comment: CRCW0402750RJNED)
RG5  ValueDisplayed: 750  [0402]  (hidden comment: CRCW0402750RJNED)
RG6  ValueDisplayed: 750  [0402]  (hidden comment: CRCW0402750RJNED)
RG7  ValueDisplayed: 750  [0402]  (hidden comment: CRCW0402750RJNED)
RG8  ValueDisplayed: 750  [0402]  (hidden comment: CRCW0402750RJNED)
RH1  ValueDisplayed: 750  [0402]  (hidden comment: CRCW0402750RJNED)
RH2  ValueDisplayed: 750  [0402]  (hidden comment: CRCW0402750RJNED)
RH3  ValueDisplayed: 750  [0402]  (hidden comment: CRCW0402750RJNED)
RH4  ValueDisplayed: 750  [0402]  (hidden comment: CRCW0402750RJNED)
RH5  ValueDisplayed: 750  [0402]  (hidden comment: CRCW0402750RJNED)
RH6  ValueDisplayed: 750  [0402]  (hidden comment: CRCW0402750RJNED)
RH7  ValueDisplayed: 750  [0402]  (hidden comment: CRCW0402750RJNED)
RH8  ValueDisplayed: 750  [0402]  (hidden comment: CRCW0402750RJNED)

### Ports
RCLKM, SER, SRCLK

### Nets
GND: C9.2 C10.2 C11.2 HC595-ROW.8(GND) HC595-ROW.13(~{OE}) HC595-ROW.17(PAD) HC595B-COLUMN.8(GND) HC595B-COLUMN.13(~{OE}) HC595B-COLUMN.17(PAD) LVC244A-COLUMN.9(GND) LVC244A-COLUMN.18(2~{OE}) LVC244A-COLUMN.20(1~{OE}) LVC244A-COLUMN.21(PAD)
QA: DA1.2(A) DA2.2(A) DA3.2(A) DA4.2(A) DA5.2(A) DA6.2(A) DA7.2(A) DA8.2(A) HC595-ROW.15(QA)
QB: DB1.2(A) DB2.2(A) DB3.2(A) DB4.2(A) DB5.2(A) DB6.2(A) DB7.2(A) DB8.2(A) HC595-ROW.1(QB)
QC: DC1.2(A) DC2.2(A) DC3.2(A) DC4.2(A) DC5.2(A) DC6.2(A) DC7.2(A) DC8.2(A) HC595-ROW.2(QC)
QD: DD1.2(A) DD2.2(A) DD3.2(A) DD4.2(A) DD5.2(A) DD6.2(A) DD7.2(A) DD8.2(A) HC595-ROW.3(QD)
QE: DE1.2(A) DE2.2(A) DE3.2(A) DE4.2(A) DE5.2(A) DE6.2(A) DE7.2(A) DE8.2(A) HC595-ROW.4(QE)
QF: DF1.2(A) DF2.2(A) DF3.2(A) DF4.2(A) DF5.2(A) DF6.2(A) DF7.2(A) DF8.2(A) HC595-ROW.5(QF)
QG: DG1.2(A) DG2.2(A) DG3.2(A) DG4.2(A) DG5.2(A) DG6.2(A) DG7.2(A) DG8.2(A) HC595-ROW.6(QG)
QH: DH1.2(A) DH2.2(A) DH3.2(A) DH4.2(A) DH5.2(A) DH6.2(A) DH7.2(A) DH8.2(A) HC595-ROW.7(QH)
QH1: HC595-ROW.14(SER) HC595B-COLUMN.9(QH')
RCLKM: HC595-ROW.12(RCLK) HC595B-COLUMN.12(RCLK) ; port RCLKM
SERM: HC595B-COLUMN.14(SER) ; port SER  [project net SER]
SRCLKM: HC595-ROW.11(SRCLK) HC595B-COLUMN.11(SRCLK) ; port SRCLK  [project net SRCLK]
VCC: C9.1 C10.1 C11.1 HC595-ROW.10(~{SRCLR}) HC595-ROW.16(VCC) HC595B-COLUMN.10(~{SRCLR}) HC595B-COLUMN.16(VCC) LVC244A-COLUMN.19(VCC)
NetDA1_1: DA1.1(K) RA1#2.1
NetDA2_1: DA2.1(K) RA2#2.1
NetDA3_1: DA3.1(K) RA3#2.1
NetDA4_1: DA4.1(K) RA4#2.1
NetDA5_1: DA5.1(K) RA5.1
NetDA6_1: DA6.1(K) RA6.1
NetDA7_1: DA7.1(K) RA7.1
NetDA8_1: DA8.1(K) RA8.1
NetDB1_1: DB1.1(K) RB1#2.1
NetDB2_1: DB2.1(K) RB2#2.1
NetDB3_1: DB3.1(K) RB3#2.1
NetDB4_1: DB4.1(K) RB4#2.1
NetDB5_1: DB5.1(K) RB5.1
NetDB6_1: DB6.1(K) RB6.1
NetDB7_1: DB7.1(K) RB7.1
NetDB8_1: DB8.1(K) RB8.1
NetDC1_1: DC1.1(K) RC1#2.1
NetDC2_1: DC2.1(K) RC2#2.1
NetDC3_1: DC3.1(K) RC3#2.1
NetDC4_1: DC4.1(K) RC4#2.1
NetDC5_1: DC5.1(K) RC5.1
NetDC6_1: DC6.1(K) RC6.1
NetDC7_1: DC7.1(K) RC7.1
NetDC8_1: DC8.1(K) RC8.1
NetDD1_1: DD1.1(K) RD1#2.1
NetDD2_1: DD2.1(K) RD2#2.1
NetDD3_1: DD3.1(K) RD3#2.1
NetDD4_1: DD4.1(K) RD4#2.1
NetDD5_1: DD5.1(K) RD5.1
NetDD6_1: DD6.1(K) RD6.1
NetDD7_1: DD7.1(K) RD7.1
NetDD8_1: DD8.1(K) RD8.1
NetDE1_1: DE1.1(K) RE1#2.1
NetDE2_1: DE2.1(K) RE2#2.1
NetDE3_1: DE3.1(K) RE3#2.1
NetDE4_1: DE4.1(K) RE4#2.1
NetDE5_1: DE5.1(K) RE5.1
NetDE6_1: DE6.1(K) RE6.1
NetDE7_1: DE7.1(K) RE7.1
NetDE8_1: DE8.1(K) RE8.1
NetDF1_1: DF1.1(K) RF1#2.1
NetDF2_1: DF2.1(K) RF2#2.1
NetDF3_1: DF3.1(K) RF3#2.1
NetDF4_1: DF4.1(K) RF4#2.1
NetDF5_1: DF5.1(K) RF5.1
NetDF6_1: DF6.1(K) RF6.1
NetDF7_1: DF7.1(K) RF7.1
NetDF8_1: DF8.1(K) RF8.1
NetDG1_1: DG1.1(K) RG1#2.1
NetDG2_1: DG2.1(K) RG2#2.1
NetDG3_1: DG3.1(K) RG3#2.1
NetDG4_1: DG4.1(K) RG4#2.1
NetDG5_1: DG5.1(K) RG5.1
NetDG6_1: DG6.1(K) RG6.1
NetDG7_1: DG7.1(K) RG7.1
NetDG8_1: DG8.1(K) RG8.1
NetDH1_1: DH1.1(K) RH1.1
NetDH2_1: DH2.1(K) RH2.1
NetDH3_1: DH3.1(K) RH3.1
NetDH4_1: DH4.1(K) RH4.1
NetDH5_1: DH5.1(K) RH5.1
NetDH6_1: DH6.1(K) RH6.1
NetDH7_1: DH7.1(K) RH7.1
NetDH8_1: DH8.1(K) RH8.1
NetHC595B-COLUMN_1: HC595B-COLUMN.1(QB) LVC244A-COLUMN.3(1A2)
NetHC595B-COLUMN_2: HC595B-COLUMN.2(QC) LVC244A-COLUMN.5(1A3)
NetHC595B-COLUMN_3: HC595B-COLUMN.3(QD) LVC244A-COLUMN.7(1A4)
NetHC595B-COLUMN_4: HC595B-COLUMN.4(QE) LVC244A-COLUMN.10(2A1)
NetHC595B-COLUMN_5: HC595B-COLUMN.5(QF) LVC244A-COLUMN.12(2A2)
NetHC595B-COLUMN_6: HC595B-COLUMN.6(QG) LVC244A-COLUMN.14(2A3)
NetHC595B-COLUMN_7: HC595B-COLUMN.7(QH) LVC244A-COLUMN.16(2A4)
NetHC595B-COLUMN_15: HC595B-COLUMN.15(QA) LVC244A-COLUMN.1(1A1)
NetLVC244A-COLUMN_2: LVC244A-COLUMN.2(2Y4) RA8.2 RB8.2 RC8.2 RD8.2 RE8.2 RF8.2 RG8.2 RH8.2
NetLVC244A-COLUMN_4: LVC244A-COLUMN.4(2Y3) RA7.2 RB7.2 RC7.2 RD7.2 RE7.2 RF7.2 RG7.2 RH7.2
NetLVC244A-COLUMN_6: LVC244A-COLUMN.6(2Y2) RA6.2 RB6.2 RC6.2 RD6.2 RE6.2 RF6.2 RG6.2 RH6.2
NetLVC244A-COLUMN_8: LVC244A-COLUMN.8(2Y1) RA5.2 RB5.2 RC5.2 RD5.2 RE5.2 RF5.2 RG5.2 RH5.2
NetLVC244A-COLUMN_11: LVC244A-COLUMN.11(1Y4) RA4#2.2 RB4#2.2 RC4#2.2 RD4#2.2 RE4#2.2 RF4#2.2 RG4#2.2 RH4.2
NetLVC244A-COLUMN_13: LVC244A-COLUMN.13(1Y3) RA3#2.2 RB3#2.2 RC3#2.2 RD3#2.2 RE3#2.2 RF3#2.2 RG3#2.2 RH3.2
NetLVC244A-COLUMN_15: LVC244A-COLUMN.15(1Y2) RA2#2.2 RB2#2.2 RC2#2.2 RD2#2.2 RE2#2.2 RF2#2.2 RG2#2.2 RH2.2
NetLVC244A-COLUMN_17: LVC244A-COLUMN.17(1Y1) RA1#2.2 RB1#2.2 RC1#2.2 RD1#2.2 RE1#2.2 RF1#2.2 RG1#2.2 RH1.2

Not connected (* = marked no-connect by the designer): HC595-ROW 9(QH')

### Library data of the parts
C9-C11 = 160R07X104KV4T: as C1 on sheet HVL166E1-7seg
DA1-DA8 DB1-DB8 DC1-DC8 DD1-DD8 DE1-DE8 DF1-DF8 DG1-DG8 DH1-DH8 = SML-311UTT86: LED, Red, SMD; Manufacturer: Rohm; Vf_V: 1.8; Value2: 1.8V; Io_A: 0.002; Value1: W; U/M: EA
HC595-ROW HC595B-COLUMN = SN74HC595BRWNR: as HC595B-1 on sheet HVL166E1-7seg
LVC244A-COLUMN = SN74LVC244ARWPR: as LVC244A-1 on sheet HVL166E1-7seg
RA1#2 RA2#2 RA3#2 RA4#2 RA5-RA8 RB1#2 RB2#2 RB3#2 RB4#2 RB5-RB8 RC1#2 RC2#2 RC3#2 RC4#2 RC5-RC8 RD1#2 RD2#2 RD3#2 RD4#2 RD5-RD8 RE1#2 RE2#2 RE3#2 RE4#2 RE5-RE8 RF1#2 RF2#2 RF3#2 RF4#2 RF5-RF8 RG1#2 RG2#2 RG3#2 RG4#2 RG5-RG8 RH1-RH8 = CRCW0402750RJNED: RES, 750, 5%, 0.063 W, 0402; Manufacturer: Vishay-Dale; CompType: Resistor; Value: 750; Value_Code: 750R; Tolerance_%: 5; Power_W: 0.063; Value2: 0.063W; VDC_V: 50; TempCo: 200 ppm/C; SizeArea_mm2: 0.5; SizeX_mm: 1; SizeZ_mm: 0.6; EIA_Code: E24; U/M: EA; AEC Category: Q200

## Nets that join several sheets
GND: HVL166E1-TI_Design_X1QFN (I2C1.1 I2C2.1 J4.20), HVL166E1-7seg (36 pins), HVL166E1-LED_Screen (13 pins)
PWM: HVL166E1-TI_Design_X1QFN (J4.19), HVL166E1-7seg (8 pins)
RCLK: HVL166E1-TI_Design_X1QFN (J4.12), HVL166E1-7seg (HC595B-1.12 HC595B-2.12 HC595B-3.12 HC595B-4.12)
RCLKM: HVL166E1-TI_Design_X1QFN (J3.5), HVL166E1-LED_Screen (HC595-ROW.12 HC595B-COLUMN.12)
SER: HVL166E1-TI_Design_X1QFN (Switch.2), HVL166E1-7seg (HC595B-1.14), HVL166E1-LED_Screen (HC595B-COLUMN.14)
SRCLK: HVL166E1-TI_Design_X1QFN (J4.13), HVL166E1-7seg (HC595B-1.11 HC595B-2.11 HC595B-3.11 HC595B-4.11), HVL166E1-LED_Screen (HC595-ROW.11 HC595B-COLUMN.11)
VCC: HVL166E1-TI_Design_X1QFN (5 pins), HVL166E1-7seg (20 pins), HVL166E1-LED_Screen (8 pins)

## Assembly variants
001: not fitted FID1 FID2 FID3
